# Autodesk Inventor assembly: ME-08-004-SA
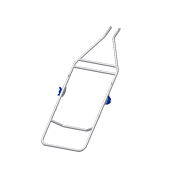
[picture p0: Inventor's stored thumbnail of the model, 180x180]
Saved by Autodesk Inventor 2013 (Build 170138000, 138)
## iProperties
Shininess: 20.0
Length Units: 11269
Angle Units: 11279
Time Units: 11290
Mass Units: 11283
Length Display Precision: 3
Angle Display Precision: 2
Created: 2001-04
Part Number: ME-08-004-SA
Document SubType Name: Baugruppe
Designer: dl
Density: 0.0
Volumn: 0.0
Area: 0.0
PropertySet Name: Model Information
Control State: 0
Master: False
Checked Out: False
Author: dl
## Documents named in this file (14)
- C:\Webworld\Webworld2014\ATC2013\Assemblies\ATC-Baby Carriage\SEAT FRAME\ME-08-004-SA.iam
- C:\Webworld\Webworld2014\ATC2013\Assemblies\ATC-Baby Carriage\SEAT FRAME\Seat_frame 515 welded.ipt
- C:\Webworld\Webworld2014\ATC2013\Assemblies\ATC-Baby Carriage\SEAT FRAME\Clamp_small.ipt
- C:\Webworld\Webworld2014\ATC2013\Assemblies\ATC-Baby Carriage\SEAT FRAME\Rivet 3mm.ipt
- C:\Webworld\Webworld2014\ATC2013\Assemblies\ATC-Baby Carriage\SEAT FRAME\DIN 986 - M6.ipt
- C:\Webworld\Webworld2014\ATC2013\Assemblies\ATC-Baby Carriage\SEAT FRAME\Push_bracket 515 complete.iam
- C:\Webworld\Webworld2014\ATC2013\Assemblies\ATC-Baby Carriage\SEAT FRAME\Coupling_Push_bracket.ipt
- C:\Webworld\Webworld2014\ATC2013\Assemblies\ATC-Baby Carriage\SEAT FRAME\Coupling_Push_bracket_drilled.ipt
- C:\Webworld\Webworld2014\ATC2013\Assemblies\ATC-Baby Carriage\SEAT FRAME\Rivet 5mm l7_5.ipt
- C:\Webworld\Webworld2014\ATC2013\Assemblies\ATC-Baby Carriage\SEAT FRAME\Joint_sheet.ipt
- C:\Webworld\Webworld2014\ATC2013\Assemblies\ATC-Baby Carriage\SEAT FRAME\Sliding_disc.ipt
- C:\Webworld\Webworld2014\ATC2013\Assemblies\ATC-Baby Carriage\SEAT FRAME\Countersunk_bolt - DIN 7991 - M6  X  70.ipt
- C:\Webworld\Webworld2014\ATC2013\Assemblies\ATC-Baby Carriage\SEAT FRAME\Sliding_disc_thick.ipt
- C:\Webworld\Webworld2014\ATC2013\Assemblies\ATC-Baby Carriage\SEAT FRAME\U-disc M6.ipt
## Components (34 placed, 13 different names)
1. Seat_frame 515 welded:1 — Mate:3, Mate:4, Mate:5, Mate:6, Mate:7, Mate:8, Mate:9, Mate:10, Mate:11, Mate:12, Mate:13, Mate:14, Mate:15, Mate:16, Mate:17, Mate:18
2. Clamp_small:1 — Insert:1, Insert:2, Mate:3, Mate:4, Mate:14
3. Clamp_small:2 — Insert:3, Insert:4, Mate:5, Mate:6, Mate:15
4. Rivet 3mm:1 — Insert:3
5. Rivet 3mm:2 — Insert:4
6. Rivet 3mm:3 — Insert:1
7. Rivet 3mm:4 — Insert:2
8. Coupling_Push_bracket_drilled:1 — Insert:5, Insert:8, Mate:8, Mate:9
9. Coupling_Push_bracket_drilled:2 — Insert:6, Insert:9, Mate:10, Mate:11, Bewegung
10. Rivet 5mm l7_5:1 — Mate:16, Mate:17
11. Rivet 5mm l7_5:2 — Mate:7, Mate:18
12. Coupling_Push_bracket:1 — Insert:5, Insert:7, Insert:23
13. Coupling_Push_bracket:2 — Insert:6, Insert:10, Bewegung, Insert:24
14. Sliding_disc:1 — Insert:8, Insert:11
15. Sliding_disc:2 — Insert:7
16. Sliding_disc:3 — Insert:10, Insert:12, Insert:16
17. Sliding_disc:4 — Insert:9
18. Joint_sheet:1 — Insert:11, Mate:2, Insert:13, Mate:12
19. Joint_sheet:2 — Insert:12, Mate:1, Insert:15, Mate:13
20. Countersunk_bolt - DIN 7991 - M6  X  70:1 — Mate:1
21. Countersunk_bolt - DIN 7991 - M6  X  70:2 — Mate:2
22. Sliding_disc_thick:1 — Insert:13, Insert:14
23. Sliding_disc_thick:2 — Insert:14, Insert:17
24. Sliding_disc_thick:3 — Insert:15, Insert:19
25. Sliding_disc_thick:4 — Insert:16
26. Coupling_Push_bracket:3 — Insert:17, Insert:18, Angle:1, Angle:2
27. Coupling_Push_bracket:4 — Insert:18, Angle:1, Insert:22, Angle:3
28. Coupling_Push_bracket:5 — Insert:19, Insert:20, Angle:3
29. Coupling_Push_bracket:6 — Insert:20, Insert:21, Angle:2
30. U-disc M6:1 — Insert:21, Insert:26
31. U-disc M6:2 — Insert:22, Insert:25
32. Push_bracket 515 complete:1 [sub-assembly] — Insert:23, Insert:24
33. DIN 986 - M6:1 — Insert:25
34. DIN 986 - M6:2 — Insert:26
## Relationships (48: Insert 26, Mate 18, Angle 4)
- Insert:1: Clamp_small:1 ↔ Rivet 3mm:3
- Insert:2: Clamp_small:1 ↔ Rivet 3mm:4
- Insert:3: Clamp_small:2 ↔ Rivet 3mm:1
- Insert:4: Clamp_small:2 ↔ Rivet 3mm:2
- Insert:5: Coupling_Push_bracket_drilled:1 ↔ Coupling_Push_bracket:1
- Insert:6: Coupling_Push_bracket_drilled:2 ↔ Coupling_Push_bracket:2
- Insert:7: Coupling_Push_bracket:1 ↔ Sliding_disc:2
- Insert:8: Coupling_Push_bracket_drilled:1 ↔ Sliding_disc:1
- Insert:9: Coupling_Push_bracket_drilled:2 ↔ Sliding_disc:4
- Insert:10: Coupling_Push_bracket:2 ↔ Sliding_disc:3
- Insert:11: Sliding_disc:1 ↔ Joint_sheet:1
- Insert:12: Sliding_disc:3 ↔ Joint_sheet:2
- Mate:1: Joint_sheet:2 ↔ Countersunk_bolt - DIN 7991 - M6  X  70:1
- Mate:2: Joint_sheet:1 ↔ Countersunk_bolt - DIN 7991 - M6  X  70:2
- Insert:13: Joint_sheet:1 ↔ Sliding_disc_thick:1
- Insert:14: Sliding_disc_thick:1 ↔ Sliding_disc_thick:2
- Insert:15: Joint_sheet:2 ↔ Sliding_disc_thick:3
- Insert:16: Sliding_disc:3 ↔ Sliding_disc_thick:4
- Insert:17: Sliding_disc_thick:2 ↔ Coupling_Push_bracket:3
- Insert:18: Coupling_Push_bracket:3 ↔ Coupling_Push_bracket:4
- Insert:19: Sliding_disc_thick:3 ↔ Coupling_Push_bracket:5
- Insert:20: Coupling_Push_bracket:5 ↔ Coupling_Push_bracket:6
- Angle:1: Coupling_Push_bracket:3 ↔ Coupling_Push_bracket:4
- Insert:21: Coupling_Push_bracket:6 ↔ U-disc M6:1
- Insert:22: Coupling_Push_bracket:4 ↔ U-disc M6:2
- Angle:2: Coupling_Push_bracket:3 ↔ Coupling_Push_bracket:6
- Angle:3: Coupling_Push_bracket:4 ↔ Coupling_Push_bracket:5
- Mate:3: Seat_frame 515 welded:1 ↔ Clamp_small:1
- Mate:4: Seat_frame 515 welded:1 ↔ Clamp_small:1
- Mate:5: Seat_frame 515 welded:1 ↔ Clamp_small:2
- Mate:6: Seat_frame 515 welded:1 ↔ Clamp_small:2
- Mate:7: Seat_frame 515 welded:1 ↔ Rivet 5mm l7_5:2
- Mate:8: Seat_frame 515 welded:1 ↔ Coupling_Push_bracket_drilled:1
- Mate:9: Seat_frame 515 welded:1 ↔ Coupling_Push_bracket_drilled:1
- Mate:10: Seat_frame 515 welded:1 ↔ Coupling_Push_bracket_drilled:2
- Mate:11: Seat_frame 515 welded:1 ↔ Coupling_Push_bracket_drilled:2
- Mate:12: Seat_frame 515 welded:1 ↔ Joint_sheet:1
- Bewegung [Angle]: Coupling_Push_bracket_drilled:2 ↔ Coupling_Push_bracket:2
- Mate:13: Seat_frame 515 welded:1 ↔ Joint_sheet:2
- Mate:14: Seat_frame 515 welded:1 ↔ Clamp_small:1
- Mate:15: Seat_frame 515 welded:1 ↔ Clamp_small:2
- Mate:16: Seat_frame 515 welded:1 ↔ Rivet 5mm l7_5:1
- Mate:17: Seat_frame 515 welded:1 ↔ Rivet 5mm l7_5:1
- Mate:18: Seat_frame 515 welded:1 ↔ Rivet 5mm l7_5:2
- Insert:23: Coupling_Push_bracket:1 ↔ Push_bracket 515 complete:1
- Insert:24: Coupling_Push_bracket:2 ↔ Push_bracket 515 complete:1
- Insert:25: U-disc M6:2 ↔ DIN 986 - M6:1
- Insert:26: U-disc M6:1 ↔ DIN 986 - M6:2
